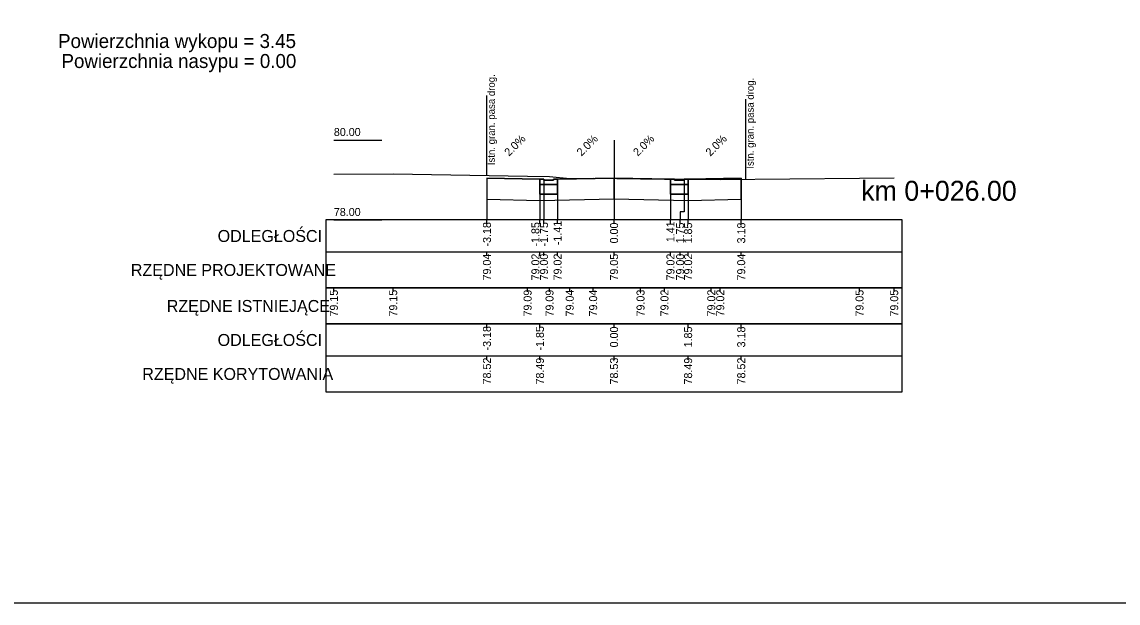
# Model space of a CAD drawing. Extents: x 7492871 to 7493499, y 5802964 to 5802992.
# Drawn here: x 7493302.12 to 7493329.51, y 5802963.88 to 5802978.41 of the extents above; entities that cross this region are included whole.
import ezdxf

# ---------------------------------------------------------------- set-up
doc = ezdxf.new("R2010")
doc.units = 0
for name, color, linetype in [('_wydruk', 7, 'Continuous'), ('d_pop_nasyp_opis', 7, 'Continuous'), ('d_pop_wykop_opis', 7, 'Continuous'), ('opisy_ramki_pop', 7, 'Continuous'), ('pop_comp_kostka', 7, 'Continuous'), ('pop_comp_lawa', 7, 'Continuous'), ('pop_comp_scieralna', 7, 'Continuous'), ('pop_granica_istn', 7, 'Continuous'), ('pop_opis', 7, 'Continuous'), ('pop_os', 7, 'Continuous'), ('pop_pikietaz', 7, 'Continuous'), ('pop_teren', 7, 'Continuous')]:
    doc.layers.add(name, color=color, linetype=linetype)

msp = doc.modelspace()

# ---------------------------------------------------------------- linework, layer by layer
msp.add_lwpolyline([(7493313.742, 5802974.503), (7493315.066, 5802974.476), (7493315.166, 5802974.476), (7493315.167, 5802974.456), (7493315.406, 5802974.456), (7493315.407, 5802974.476), (7493315.507, 5802974.476), (7493316.917, 5802974.504), (7493318.327, 5802974.476), (7493318.427, 5802974.476), (7493318.428, 5802974.456), (7493318.667, 5802974.456), (7493318.668, 5802974.476), (7493318.768, 5802974.476), (7493320.095, 5802974.503)])
at = {"layer": '_wydruk'}
msp.add_lwpolyline([(7492871.369, 5802992.281), (7493499.283, 5802992.281), (7493499.283, 5802963.881), (7492871.369, 5802963.881)], close=True, dxfattribs=at)
at = {"layer": 'opisy_ramki_pop'}
for points in [[(7493313.742, 5802973.982), (7493313.742, 5802973.659), (7493313.742, 5802973.659), (7493313.742, 5802973.459)], [(7493316.917, 5802973.984), (7493316.917, 5802973.659), (7493316.917, 5802973.659), (7493316.917, 5802973.459)], [(7493320.095, 5802973.982), (7493320.095, 5802973.659), (7493320.095, 5802973.659), (7493320.095, 5802973.459)], [(7493315.066, 5802973.947), (7493315.066, 5802973.659), (7493315.066, 5802973.659), (7493315.066, 5802973.459)], [(7493318.768, 5802973.947), (7493318.768, 5802973.659), (7493318.768, 5802973.659), (7493318.768, 5802973.459)]]:
    msp.add_lwpolyline(points, dxfattribs=at)
at = {"layer": 'pop_comp_kostka'}
for p, q in [((7493315.166, 5802974.476), (7493315.066, 5802974.476)), ((7493315.066, 5802974.476), (7493315.066, 5802974.346)), ((7493315.066, 5802974.346), (7493315.507, 5802974.346)), ((7493315.167, 5802974.456), (7493315.166, 5802974.476)), ((7493315.406, 5802974.456), (7493315.167, 5802974.456)), ((7493315.407, 5802974.476), (7493315.406, 5802974.456)), ((7493315.507, 5802974.476), (7493315.407, 5802974.476)), ((7493315.507, 5802974.346), (7493315.507, 5802974.476)), ((7493318.427, 5802974.476), (7493318.327, 5802974.476)), ((7493318.327, 5802974.476), (7493318.327, 5802974.346)), ((7493318.327, 5802974.346), (7493318.768, 5802974.346)), ((7493318.428, 5802974.456), (7493318.427, 5802974.476)), ((7493318.667, 5802974.456), (7493318.428, 5802974.456)), ((7493318.668, 5802974.476), (7493318.667, 5802974.456)), ((7493318.768, 5802974.476), (7493318.668, 5802974.476)), ((7493318.768, 5802974.346), (7493318.768, 5802974.476))]:
    msp.add_line(p, q, dxfattribs=at)
at = {"layer": 'pop_comp_lawa'}
for p, q in [((7493315.507, 5802974.346), (7493315.066, 5802974.346)), ((7493315.066, 5802974.346), (7493315.066, 5802974.106)), ((7493315.507, 5802974.106), (7493315.507, 5802974.346)), ((7493318.768, 5802974.346), (7493318.327, 5802974.346)), ((7493318.327, 5802974.346), (7493318.327, 5802974.106)), ((7493318.768, 5802974.106), (7493318.768, 5802974.346)), ((7493315.066, 5802974.106), (7493315.507, 5802974.106)), ((7493318.327, 5802974.106), (7493318.768, 5802974.106))]:
    msp.add_line(p, q, dxfattribs=at)
at = {"layer": 'pop_comp_scieralna'}
for p, q in [((7493315.066, 5802974.476), (7493313.742, 5802974.503)), ((7493313.742, 5802974.503), (7493313.742, 5802973.982)), ((7493316.917, 5802974.504), (7493315.507, 5802974.476)), ((7493316.917, 5802973.984), (7493316.917, 5802974.504)), ((7493318.327, 5802974.476), (7493316.917, 5802974.504)), ((7493316.917, 5802974.504), (7493316.917, 5802973.984)), ((7493320.095, 5802974.503), (7493318.768, 5802974.476)), ((7493320.095, 5802973.982), (7493320.095, 5802974.503)), ((7493315.066, 5802974.106), (7493315.066, 5802974.476)), ((7493315.507, 5802974.476), (7493315.507, 5802974.106)), ((7493318.327, 5802974.106), (7493318.327, 5802974.476)), ((7493318.768, 5802974.476), (7493318.768, 5802974.106)), ((7493313.742, 5802973.982), (7493315.066, 5802973.947)), ((7493315.507, 5802974.106), (7493315.066, 5802974.106)), ((7493315.066, 5802973.947), (7493316.917, 5802973.984)), ((7493316.917, 5802973.984), (7493318.768, 5802973.947)), ((7493318.768, 5802974.106), (7493318.327, 5802974.106)), ((7493318.768, 5802973.947), (7493320.095, 5802973.982))]:
    msp.add_line(p, q, dxfattribs=at)
at = {"layer": 'pop_granica_istn'}
for p, q in [((7493313.742, 5802975.068), (7493313.742, 5802976.568)), ((7493320.21, 5802974.98), (7493320.21, 5802976.48)), ((7493313.742, 5802974.568), (7493313.742, 5802975.068)), ((7493320.21, 5802974.48), (7493320.21, 5802974.98))]:
    msp.add_line(p, q, dxfattribs=at)
at = {"layer": 'pop_opis'}
for p, q in [((7493309.917, 5802975.459), (7493311.117, 5802975.459)), ((7493309.717, 5802973.459), (7493309.717, 5802971.759)), ((7493309.717, 5802973.459), (7493309.717, 5802971.759)), ((7493309.717, 5802973.459), (7493309.717, 5802971.759)), ((7493309.717, 5802973.459), (7493309.717, 5802971.759)), ((7493309.917, 5802973.459), (7493311.117, 5802973.459)), ((7493313.742, 5802973.359), (7493313.742, 5802973.459)), ((7493315.066, 5802973.359), (7493315.066, 5802973.459)), ((7493315.167, 5802973.359), (7493315.167, 5802973.459)), ((7493315.507, 5802973.359), (7493315.507, 5802973.459)), ((7493316.917, 5802973.359), (7493316.917, 5802973.459)), ((7493318.327, 5802973.359), (7493318.327, 5802973.459)), ((7493318.568, 5802973.359), (7493318.568, 5802973.459)), ((7493318.768, 5802973.359), (7493318.768, 5802973.459)), ((7493320.095, 5802973.359), (7493320.095, 5802973.459)), ((7493309.717, 5802972.659), (7493324.117, 5802972.659)), ((7493309.717, 5802972.659), (7493324.117, 5802972.659)), ((7493309.717, 5802972.659), (7493324.117, 5802972.659)), ((7493309.717, 5802972.659), (7493324.117, 5802972.659)), ((7493313.742, 5802972.559), (7493313.742, 5802972.659)), ((7493315.066, 5802972.559), (7493315.066, 5802972.659)), ((7493315.167, 5802972.559), (7493315.167, 5802972.659)), ((7493315.507, 5802972.559), (7493315.507, 5802972.659)), ((7493316.917, 5802972.559), (7493316.917, 5802972.659)), ((7493318.327, 5802972.559), (7493318.327, 5802972.659)), ((7493318.568, 5802972.559), (7493318.568, 5802972.659)), ((7493318.768, 5802972.559), (7493318.768, 5802972.659)), ((7493320.095, 5802972.559), (7493320.095, 5802972.659)), ((7493309.717, 5802971.759), (7493309.717, 5802970.859)), ((7493309.917, 5802971.659), (7493309.917, 5802971.759)), ((7493311.399, 5802971.659), (7493311.399, 5802971.759)), ((7493314.758, 5802971.659), (7493314.758, 5802971.759)), ((7493315.306, 5802971.659), (7493315.306, 5802971.759)), ((7493315.81, 5802971.659), (7493315.81, 5802971.759)), ((7493316.395, 5802971.659), (7493316.395, 5802971.759)), ((7493317.579, 5802971.659), (7493317.579, 5802971.759)), ((7493318.177, 5802971.659), (7493318.177, 5802971.759)), ((7493319.347, 5802971.659), (7493319.347, 5802971.759)), ((7493319.571, 5802971.659), (7493319.571, 5802971.759)), ((7493323.05, 5802971.659), (7493323.05, 5802971.759)), ((7493323.917, 5802971.659), (7493323.917, 5802971.759)), ((7493309.717, 5802970.859), (7493309.717, 5802969.159)), ((7493313.742, 5802970.759), (7493313.742, 5802970.859)), ((7493315.066, 5802970.759), (7493315.066, 5802970.859)), ((7493316.917, 5802970.759), (7493316.917, 5802970.859)), ((7493318.768, 5802970.759), (7493318.768, 5802970.859)), ((7493320.095, 5802970.759), (7493320.095, 5802970.859)), ((7493309.717, 5802970.059), (7493324.117, 5802970.059)), ((7493313.742, 5802969.959), (7493313.742, 5802970.059)), ((7493315.066, 5802969.959), (7493315.066, 5802970.059)), ((7493316.917, 5802969.959), (7493316.917, 5802970.059)), ((7493318.768, 5802969.959), (7493318.768, 5802970.059)), ((7493320.095, 5802969.959), (7493320.095, 5802970.059))]:
    msp.add_line(p, q, dxfattribs=at)
for points in [[(7493313.742, 5802974.503), (7493313.742, 5802973.659), (7493313.742, 5802973.659), (7493313.742, 5802973.459)], [(7493316.917, 5802974.504), (7493316.917, 5802973.659), (7493316.917, 5802973.659), (7493316.917, 5802973.459)], [(7493320.095, 5802974.503), (7493320.095, 5802973.659), (7493320.095, 5802973.659), (7493320.095, 5802973.459)], [(7493315.066, 5802974.476), (7493315.066, 5802973.659), (7493315.066, 5802973.659), (7493315.066, 5802973.459)], [(7493315.167, 5802974.456), (7493315.167, 5802973.659), (7493315.167, 5802973.659), (7493315.167, 5802973.459)], [(7493315.507, 5802974.476), (7493315.507, 5802973.659), (7493315.507, 5802973.659), (7493315.507, 5802973.459)], [(7493318.327, 5802974.476), (7493318.327, 5802973.659), (7493318.327, 5802973.659), (7493318.327, 5802973.459)], [(7493318.667, 5802974.456), (7493318.667, 5802973.659), (7493318.568, 5802973.659), (7493318.568, 5802973.459)], [(7493318.768, 5802974.476), (7493318.768, 5802973.659), (7493318.768, 5802973.659), (7493318.768, 5802973.459)]]:
    msp.add_lwpolyline(points, dxfattribs=at)
for points in [[(7493309.717, 5802973.459), (7493309.717, 5802971.759), (7493324.117, 5802971.759), (7493324.117, 5802973.459)], [(7493309.717, 5802973.459), (7493309.717, 5802971.759), (7493324.117, 5802971.759), (7493324.117, 5802973.459)], [(7493309.717, 5802973.459), (7493309.717, 5802971.759), (7493324.117, 5802971.759), (7493324.117, 5802973.459)], [(7493309.717, 5802973.459), (7493309.717, 5802971.759), (7493324.117, 5802971.759), (7493324.117, 5802973.459)], [(7493309.717, 5802971.759), (7493309.717, 5802970.859), (7493324.117, 5802970.859), (7493324.117, 5802971.759)], [(7493309.717, 5802970.859), (7493309.717, 5802969.159), (7493324.117, 5802969.159), (7493324.117, 5802970.859)]]:
    msp.add_lwpolyline(points, close=True, dxfattribs=at)
at = {"layer": 'pop_os'}
msp.add_line((7493316.917, 5802975.459), (7493316.917, 5802973.459), dxfattribs=at)
at = {"layer": 'pop_teren'}
msp.add_lwpolyline([(7493309.917, 5802974.605), (7493311.399, 5802974.613), (7493314.758, 5802974.552), (7493315.306, 5802974.547), (7493315.81, 5802974.499), (7493316.395, 5802974.504), (7493317.579, 5802974.49), (7493318.177, 5802974.482), (7493319.347, 5802974.478), (7493319.571, 5802974.474), (7493323.05, 5802974.504), (7493323.917, 5802974.512)], dxfattribs=at)

# ---------------------------------------------------------------- texts
at = {"layer": 'd_pop_nasyp_opis'}
msp.add_text('Powierzchnia nasypu = 0.00', height=0.35, dxfattribs=at).set_placement((7493303.112, 5802977.259))
at = {"layer": 'd_pop_wykop_opis'}
msp.add_text('Powierzchnia wykopu = 3.45', height=0.35, dxfattribs=at).set_placement((7493303.027, 5802977.759))
at = {"layer": 'pop_granica_istn'}
for p in [(7493313.94, 5802974.829), (7493320.408, 5802974.741)]:
    msp.add_text('Istn. gran. pasa drog.', height=0.18, rotation=90, dxfattribs=at).set_placement(p)
at = {"layer": 'pop_opis'}
for s, height, p in [('80.00', 0.2, (7493309.917, 5802975.559)), ('78.00', 0.2, (7493309.917, 5802973.559)), ('ODLEGŁOŚCI', 0.3, (7493307.013, 5802972.909)), ('ODLEGŁOŚCI', 0.3, (7493307.013, 5802972.909)), ('ODLEGŁOŚCI', 0.3, (7493307.013, 5802972.909)), ('ODLEGŁOŚCI', 0.3, (7493307.013, 5802972.909)), ('RZĘDNE PROJEKTOWANE', 0.3, (7493304.845, 5802972.059)), ('RZĘDNE PROJEKTOWANE', 0.3, (7493304.845, 5802972.059)), ('RZĘDNE PROJEKTOWANE', 0.3, (7493304.845, 5802972.059)), ('RZĘDNE PROJEKTOWANE', 0.3, (7493304.845, 5802972.059)), ('RZĘDNE ISTNIEJĄCE', 0.3, (7493305.742, 5802971.159)), ('ODLEGŁOŚCI', 0.3, (7493307.013, 5802970.309)), ('RZĘDNE KORYTOWANIA', 0.3, (7493305.131, 5802969.459))]:
    msp.add_text(s, height=height, dxfattribs=at).set_placement(p)
for s, rotation, p in [('2.0%', 45, (7493314.295, 5802975.039)), ('2.0%', 45, (7493316.103, 5802975.04)), ('2.0%', 45, (7493317.513, 5802975.04)), ('2.0%', 45, (7493319.323, 5802975.039)), ('-1.41', 90, (7493315.607, 5802972.829)), ('1.41', 90, (7493318.427, 5802972.905)), ('-3.18', 90, (7493313.842, 5802972.797)), ('-1.85', 90, (7493315.053, 5802972.796)), ('-1.75', 90, (7493315.267, 5802972.796)), ('0.00', 90, (7493317.017, 5802972.874)), ('1.75', 90, (7493318.668, 5802972.873)), ('1.85', 90, (7493318.868, 5802972.873)), ('3.18', 90, (7493320.195, 5802972.873)), ('79.04', 90, (7493313.842, 5802971.947)), ('79.02', 90, (7493315.053, 5802971.948)), ('79.00', 90, (7493315.267, 5802971.947)), ('79.02', 90, (7493315.607, 5802971.948)), ('79.05', 90, (7493317.017, 5802971.945)), ('79.02', 90, (7493318.427, 5802971.948)), ('79.00', 90, (7493318.668, 5802971.947)), ('79.02', 90, (7493318.868, 5802971.948)), ('79.04', 90, (7493320.195, 5802971.947)), ('79.15', 90, (7493310.017, 5802971.045)), ('79.15', 90, (7493311.499, 5802971.045)), ('79.09', 90, (7493314.858, 5802971.046)), ('79.09', 90, (7493315.406, 5802971.046)), ('79.04', 90, (7493315.91, 5802971.047)), ('79.04', 90, (7493316.495, 5802971.047)), ('79.03', 90, (7493317.679, 5802971.047)), ('79.02', 90, (7493318.277, 5802971.048)), ('79.02', 90, (7493319.447, 5802971.048)), ('79.02', 90, (7493319.671, 5802971.048)), ('79.05', 90, (7493323.15, 5802971.045)), ('79.05', 90, (7493324.017, 5802971.045)), ('-3.18', 90, (7493313.842, 5802970.197)), ('-1.85', 90, (7493315.166, 5802970.196)), ('0.00', 90, (7493317.017, 5802970.274)), ('1.85', 90, (7493318.868, 5802970.273)), ('3.18', 90, (7493320.195, 5802970.273)), ('78.52', 90, (7493313.842, 5802969.348)), ('78.49', 90, (7493315.166, 5802969.346)), ('78.53', 90, (7493317.017, 5802969.347)), ('78.49', 90, (7493318.868, 5802969.346)), ('78.52', 90, (7493320.195, 5802969.348))]:
    msp.add_text(s, height=0.2, rotation=rotation, dxfattribs=at).set_placement(p)
at = {"layer": 'pop_pikietaz'}
msp.add_text('km 0+026.00', height=0.5, dxfattribs=at).set_placement((7493323.093, 5802973.939))

doc.saveas('drawing.dxf')
